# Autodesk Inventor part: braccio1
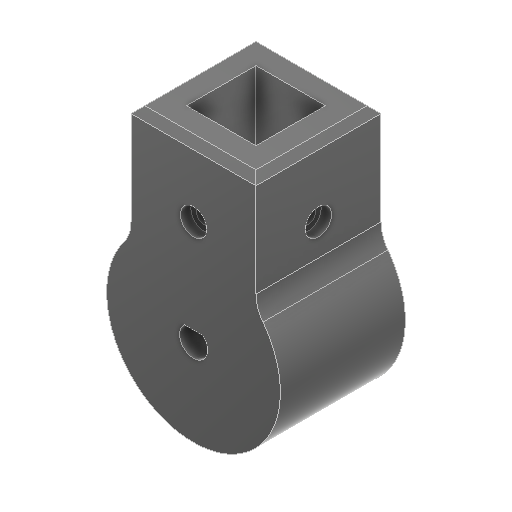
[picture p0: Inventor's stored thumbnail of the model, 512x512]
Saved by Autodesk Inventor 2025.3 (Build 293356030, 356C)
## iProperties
Created: 2026-03
Part Number: braccio1
Material: Plastica ABS
Document SubType Name: Modeling
Designer: R5800u
Density: 1.06 g/cm^3
Appearance: Liscia - Nero
Author: R5800u
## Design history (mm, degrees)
sketch "Schizzo1"
  geometry: L1 (-2.646, 3)-(2.646, 3); C1 r 25 at (0, 0); A1 r 4 centre (0, 0) between (-2.646, 3) and (2.646, 3); 1 further point
  constraints: 2 centre point, 2 coincident, 2 end point, 2 point on circle, 1 horizontal
  dimensions: "d0" = 50 diameter of C1; "d1" = 8 diameter of A1; "d2" = 3 distance from line of point (0, 0) L1
extrude "Estrusione1" new body sketch "Schizzo1" stored distance "d3" = 36; taper "d4" = 0 deg
node "Piano di lavoro1"
sketch "Schizzo2"
  geometry: L1 (18, 18)-(-18, 18); L2 (-18, 18)-(-18, -18); L3 (-18, -18)-(18, -18); L4 (18, -18)-(18, 18); L5 (18, 18)-(-18, -18); L6 (-18, 18)-(18, -18); L7 (10, 10)-(-10, 10); L8 (-10, 10)-(-10, -10); L9 (-10, -10)-(10, -10); L10 (10, -10)-(10, 10); L11 (10, 10)-(-10, -10); L12 (-10, 10)-(10, -10); 1 further point
  constraints: 24 end point, 4 midpoint, 4 parallel, 2 horizontal, 2 perpendicular
  dimensions: "d6" = 36 distance of L3.end L2.end; "d7" = 36 distance of L2.end L1.end; "d8" = 20 distance of L9.end L8.end; "d9" = 20 distance of L8.end L7.end
extrude "Estrusione2" join sketch "Schizzo2" stored distance "d10" = 10; taper "d11" = 0 deg
sketch "Schizzo3"
  geometry: L1 (-10, 50)-(10, 50) reference; L2 (0, 50)-(0, 30); 1 further point
  constraints: 2 end point, 1 midpoint, 1 vertical
  dimensions: "d16" = 20 distance of L2.start L2.end
hole "Foro1" sketch "Schizzo3" at (0, 30) diameter "d17" = 4.3; stored, may be unused: countersink angle "d21" = 90 deg, drill point angle "d23" = 118 deg; dims "d18" = 6, "d19" = 7.5, "d20" = 3, "d22" = 8
pattern_circular "Serie circolare1" dims angle "d25" = 360 deg
chamfer "Smusso2" distance "d27" = 2; stored, may be unused: second distance "d28" = 2, angle "d29" = 45 deg
fillet "Raccordo2" dims "d30" = 10
node "Solido1"
